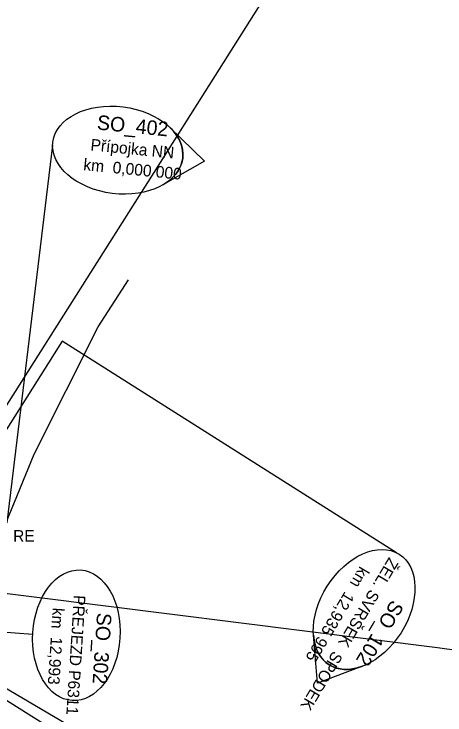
# Model space of a CAD drawing. Extents: x -743359 to -742769, y -1127804 to -1126284.
# Drawn here: x -743151.7 to -743077.7, y -1127113.5 to -1126992.9 of the extents above; entities that cross this region are included whole.
import ezdxf

# ---------------------------------------------------------------- set-up
doc = ezdxf.new("R2010")
doc.units = 0
for name, color, linetype in [('_Násyp', 7, 'Continuous'), ('_TRASA_vedení kabelu_CEZ', 7, 'Continuous'), ('_Zabezpečovací zařízení_trasa', 7, 'Continuous'), ('bublina_fialová_čára_tenká', 7, 'Continuous'), ('bublina_fialová_čára_tučná', 7, 'Continuous'), ('bublina_růžová_230_čára_tučná', 7, 'Continuous'), ('SMER_VYS_VYROVNANI', 7, 'Continuous')]:
    doc.layers.add(name, color=color, linetype=linetype)

msp = doc.modelspace()

# ---------------------------------------------------------------- linework, layer by layer
at = {"layer": '_TRASA_vedení kabelu_CEZ'}
for points in [[(-743153.07, -1127080.41), (-743148.26, -1127068.65), (-743137.26, -1127046.76), (-743132.07, -1127038.68)], [(-743154.26, -1127082.61), (-743159.25, -1127091.79), (-743078.98, -1127101.9), (-743017.04, -1127110.61), (-742993.93, -1127114.82), (-742964.82, -1127120.76), (-742937.74, -1127126.54), (-742940.65, -1127140.7), (-742943, -1127146.4)]]:
    msp.add_lwpolyline(points, dxfattribs=at)
at = {"layer": '_Zabezpečovací zařízení_trasa'}
msp.add_lwpolyline([(-743098.65, -1126974.15), (-743125.94, -1127017.38), (-743152.6, -1127059.61), (-743175.02, -1127095.12), (-743199.16, -1127133.35), (-743215.97, -1127159.94), (-743232.82, -1127186.51), (-743247.46, -1127209.81), (-743254.52, -1127221.64), (-743261.3, -1127233.69), (-743264.16, -1127239.2), (-743264.86, -1127241.11), (-743267.34, -1127245.82), (-743268.29, -1127247.16), (-743271.71, -1127253.75), (-743281.12, -1127274.2), (-743291.92, -1127301.42), (-743296.72, -1127315.22), (-743301.12, -1127329.13), (-743306.79, -1127349.51), (-743311.54, -1127370.06), (-743315.69, -1127392.87), (-743318.79, -1127415.84)], dxfattribs=at)
at = {"layer": 'bublina_fialová_čára_tenká'}
for p, q in [((-743145.09, -1127015.48), (-743152.93, -1127080.48)), ((-743086, -1127085.59), (-743143.43, -1127049.19)), ((-743129.51, -1127122.8), (-743175.48, -1127095.85)), ((-743148.5, -1127099.64), (-743174.29, -1127097.71)), ((-743109.42, -1127138.31), (-743174.12, -1127097.81))]:
    msp.add_line(p, q, dxfattribs=at)
at = {"layer": 'bublina_fialová_čára_tučná'}
msp.add_ellipse((-743141, -1127099.79), major_axis=(0.72, 11.23), ratio=0.666667, dxfattribs=at)
at = {"layer": 'bublina_růžová_230_čára_tučná'}
for p, q in [((-743124.92, -1127012.47), (-743119, -1127018.23)), ((-743124.92, -1127012.47), (-743119, -1127018.23)), ((-743119, -1127018.23), (-743126.16, -1127022.35)), ((-743119, -1127018.23), (-743126.16, -1127022.35)), ((-743099.58, -1127108.03), (-743100.27, -1127099.8)), ((-743099.58, -1127108.03), (-743100.27, -1127099.8)), ((-743091.85, -1127105.13), (-743099.58, -1127108.03)), ((-743091.85, -1127105.13), (-743099.58, -1127108.03))]:
    msp.add_line(p, q, dxfattribs=at)
for centre, major_axis in [((-743133.89, -1127016.36), (-11.16, 1.4)), ((-743091.56, -1127095.35), (6.01, 9.51))]:
    msp.add_ellipse(centre, major_axis=major_axis, ratio=0.666667, dxfattribs=at)
for centre, major_axis in [((-743133.89, -1127016.36), (11.16, -1.4)), ((-743091.56, -1127095.35), (-6.02, -9.51))]:
    msp.add_ellipse(centre, major_axis=major_axis, ratio=0.666473, start_param=5.557317, end_param=7.009053, dxfattribs=at)
at = {"layer": 'SMER_VYS_VYROVNANI'}
msp.add_lwpolyline([(-743143.43, -1127049.19), (-743169.53, -1127090.54)], dxfattribs=at)

# ---------------------------------------------------------------- texts
at = {"layer": '_Násyp'}
for s, height, rotation, p in [('SO_402', 2.5, 354.3558, (-743137.54, -1127012.8)), ('Přípojka NN', 2, 354.3558, (-743138.64, -1127016.39)), ('km  0,000 000', 2, 354.3558, (-743139.87, -1127019.79)), ('ŽEL. SVRŠEK  SPODEK', 2, 239.1744, (-743087.27, -1127086.27)), ('km  12,935 995', 2, 239.1744, (-743092.27, -1127087.8)), ('PŘEJEZD P6311', 2, 266.3528, (-743141.42, -1127092.84)), ('SO_102', 2.5, 239.1744, (-743086.78, -1127093.56)), ('km  12,993', 2, 266.3528, (-743145.07, -1127095.02)), ('SO_302', 2.5, 266.3528, (-743137.44, -1127095.87))]:
    msp.add_text(s, height=height, rotation=rotation, dxfattribs=at).set_placement(p)
at = {"layer": '_TRASA_vedení kabelu_CEZ'}
msp.add_text('RE', height=2, dxfattribs=at).set_placement((-743151.87, -1127083.71))

doc.saveas('drawing.dxf')
